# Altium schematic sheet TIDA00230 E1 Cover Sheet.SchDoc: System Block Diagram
size 431 x 279 mm; Date: Not shown in title block; ApprovedBy: Not shown in title block; CheckedBy: Not shown in title block; Author: Not shown in title block; CompanyName: Not shown in title block; DrawnBy: M. Chevrier; Engineer: Not shown in title block; Organization: Not shown in title block; Address1: Not shown in title block; Address2: Not shown in title block; Address3: Not shown in title block; Address4: Not shown in title block; DocumentNumber: 1; Revision: Use project parameter SCH_Rev; SheetNumber: 1; SheetTotal: 1; PageSetup: Record=PageOptions|CenterHorizontal=True|CenterVertical=True|PrintScale=1.00|XCorrection=1.00|YCorrection=1.00|PrintKind=0|BorderSize=5000000|LeftOffset=0|BottomOffset=0|Orientation=2|PaperLength=1000|PaperWidth=1000|Scale=100|PaperSource=15|PrintQuality=600|MediaType=1|DitherType=10|PaperKind=Letter|PrintScaleMode=1
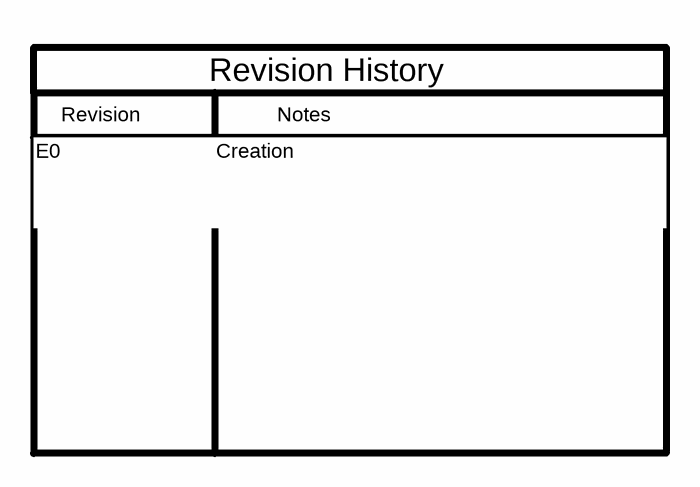
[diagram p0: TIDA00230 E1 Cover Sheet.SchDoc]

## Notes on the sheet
- Revision
- Notes
- Revision History
- E0
- Creation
